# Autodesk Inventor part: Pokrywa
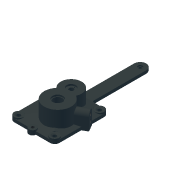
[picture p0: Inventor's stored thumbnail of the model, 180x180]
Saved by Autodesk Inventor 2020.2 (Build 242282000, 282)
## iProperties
Created: 2006-02
Part Number: Pokrywa
Document SubType Name: Modeling
Designer: F.Stasiak
Density: 1 g/cm^3
Material: Ogólny
Appearance: Brąz armatni (nowy/polerowany)
Manager: www.cadconsulting.pl
Company: Fabian Stasiak CAD Consulting
Author: F.Stasiak
Subject: Zbiór ćwiczeń. Autodesk Inventor 2020. Kurs podstawowy
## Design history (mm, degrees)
sketch "Szkic1"
  geometry: L1 (-75, 90)-(75, 90); L2 (75, 90)-(75, -90); L3 (75, -90)-(-75, -90); L4 (-75, -90)-(-75, 90); L5 (0, 90)-(0, -90); L6 (-20, 90)-(-20, 290); L7 (-20, 290)-(20, 290); L8 (20, 290)-(20, 90); L9 (0, 290)-(0, 90); 2 further points
  constraints: 18 end point, 4 midpoint, 4 perpendicular, 3 parallel, 2 point on line, 1 coincident, 1 horizontal
  dimensions: "d0" = 150 distance of L2.end L3.end; "d1" = 180 distance of L1.end L2.end; "d173" = 380 distance between parallel lines of L7 L3; "d174" = 40 distance of L6.end L7.end
extrude "Wyciągnięcie proste1" new body sketch "Szkic1" distance "d2" = 10; taper "d3" = 0 deg
node "Płaszczyzna konstrukcyjna1"
sketch "Szkic4"
  geometry: L1 (75, 90)-(75, -90) reference; L2 (-75, 90)-(75, 90) reference; L3 (-75, -90)-(-75, 90) reference; L4 (75, -90)-(-75, -90) reference; L5 (-15, 30)-(15, 30); L6 (15, 30)-(15, -30); L7 (15, -30)-(-15, -30); L8 (-15, -30)-(-15, 30)
  constraints: 8 end point, 3 other
feature "Wyciągnięcie złożone1" sketch "Szkic4" dims "d17" = 0, "d18" = 90 deg, "d19" = 0, "d20" = 90 deg
  node "Krawędzie1"
sketch "Szkic5"
  geometry: C1 r 45 at (-15, -20); 1 further point
  constraints: 1 centre point
  dimensions: "d21" = 90 diameter of C1
extrude "Wyciągnięcie proste4" join sketch "Szkic5" distance "d24" = 70; taper "d25" = 0 deg
sketch "Szkic6"
  geometry: C1 r 35 at (5, 45); 1 further point
  constraints: 1 centre point
  dimensions: "d26" = 70 diameter of C1
extrude "Wyciągnięcie proste5" join sketch "Szkic6" distance "d29" = 60; taper "d30" = 0 deg
fillet "Zaokrąglenie4" dims "d33" = 15
extrude "Wyciągnięcie proste25" join sketch "Szkic1" distance "d175" = 10; taper "d176" = 0 deg
fillet "Zaokrąglenie16" dims "d177" = 5, "d178" = 20
hole "Otwór8" diameter "d181" = 10; stored, may be unused: countersink angle "d185" = 90 deg, drill point angle "d187" = 118 deg; dims "d179" = 10, "d180" = 10, "d182" = 6, "d183" = 15, "d184" = 4, "d186" = 8
feature "Skorupa1" dims "d35" = 3
sketch "Szkic13"
  geometry: C1 r 15 at (-60, 75); C2 r 15 at (60, 75); C3 r 15 at (60, -75); C4 r 15 at (-60, -75); A1 r 15 centre (-60, 75) between (-60, 90) and (-75, 75) reference; A2 r 15 centre (60, 75) between (75, 75) and (60, 90) reference; A3 r 15 centre (-60, -75) between (-75, -75) and (-60, -90) reference; A4 r 15 centre (60, -75) between (60, -90) and (75, -75) reference
  constraints: 4 centre point, 4 coincident, 4 concentric
extrude "Wyciągnięcie proste11" join sketch "Szkic13" distance "d55" = 15; taper "d56" = 0 deg
sketch "Szkic14"
  geometry: C1 r 15 at (-60, -75); C2 r 15 at (60, -75); C3 r 15 at (60, 75); C4 r 15 at (-60, 75); A1 r 15 centre (60, -75) between (45.858, -70) and (55, -60.858) reference; A2 r 15 centre (-60, -75) between (-55, -60.858) and (-45.858, -70) reference; A3 r 15 centre (-60, 75) between (-45.858, 70) and (-55, 60.858) reference; A4 r 15 centre (60, 75) between (55, 60.858) and (45.858, 70) reference
  constraints: 4 centre point, 4 coincident, 4 concentric
extrude "Wyciągnięcie proste12" cut sketch "Szkic14" distance "d57" = 15; taper "d58" = 0 deg
fillet "Zaokrąglenie10" dims "d60" = 3
node "Oś konstrukcyjna2"
node "Płaszczyzna konstrukcyjna4"
node "Płaszczyzna konstrukcyjna5"
sketch "Szkic21"
  geometry: L1 (0, -52.272)-(0, 77.631) reference; L2 (15, -14)-(15, 14); L3 (15, 14)-(40, 14); L4 (40, -14)-(15, -14); L5 (-7, 0)-(91, 0) reference; A1 r 14 centre (40, 0) between (40, -14) and (40, 14)
  constraints: 6 end point, 2 perpendicular, 2 point on circle, 2 tangent, 1 centre point, 1 parallel, 1 point on line
  dimensions: "d92" = 14 radius of A1; "d93" = 25 distance of L4.start L2.start; "d96" = 40 distance from line of L1 A1.centre
extrude "Wyciągnięcie proste18" join sketch "Szkic21" stored distance "d94" = 10; taper "d95" = 0 deg; dims "d21" = 90
sketch "Szkic22"
  geometry: L1 (0, 18.644)-(0, 0) reference; L2 (-22.282, 31.509)-(0, 18.644) reference; L3 (-22.282, 31.509)-(-36.282, 7.26) reference; L4 (-36.282, 7.26)-(-4.037, -11.356) reference; A1 r 45 centre (40, -20.616) between (0, 0) and (-4.037, -11.356) reference
extrude "Wyciągnięcie proste19" join sketch "Szkic22" stored distance "d97" = 10; taper "d98" = 0 deg
sketch "Szkic23"
  geometry: L1 (-75, 30.807)-(-75, -1.525) reference; L2 (-75, 30.807)-(-77.282, 32.124) reference; L3 (-77.282, 32.124)-(-91.282, 7.876) reference; L4 (-91.282, 7.876)-(-75, -1.525) reference
extrude "Wyciągnięcie proste20" join sketch "Szkic23" stored distance "d99" = 10; taper "d100" = 0 deg
hole "Otwór1" diameter "d103" = 10.106; stored, may be unused: countersink angle "d107" = 90 deg, drill point angle "d109" = 118 deg; dims "d101" = 10, "d102" = 10, "d104" = 6, "d105" = 4, "d106" = 2, "d108" = 20
sketch "Szkic24"
  geometry: L1 (-40, 0)-(-20, 0); C1 r 5.053 at (-40, 0) reference; 1 further point
  constraints: 2 end point, 1 coincident, 1 horizontal
  dimensions: "d110" = 20 distance of L1.start L1.end
hole "Otwór2" sketch "Szkic24" at (-20, 0) diameter "d111" = 10.106; stored, may be unused: countersink angle "d115" = 90 deg, drill point angle "d117" = 118 deg; dims "d112" = 6, "d113" = 4, "d114" = 2, "d116" = 20
sketch "Szkic25"
  geometry: C1 r 42 at (0, 0) reference; C2 r 20 at (0, 0)
  constraints: 1 centre point, 1 coincident
  dimensions: "d118" = 40 diameter of C2
extrude "Wyciągnięcie proste21" join sketch "Szkic25" distance "d119" = 30; taper "d120" = 0 deg
hole "Otwór3" diameter "d123" = 30; stored, may be unused: countersink angle "d127" = 90 deg, drill point angle "d129" = 118 deg; dims "d121" = 10, "d122" = 10, "d124" = 6, "d125" = 35, "d126" = 5, "d128" = 8
sketch "Szkic26"
  geometry: C1 r 17.5 at (0, 0); A1 r 42 centre (0, -68.007) between (14.427, -28.563) and (-14.427, -28.563) reference; A2 r 32 centre (0, 0) between (14.427, -28.563) and (-14.427, -28.563) reference
  constraints: 1 centre point, 1 coincident
  dimensions: "d130" = 35 diameter of C1
extrude "Wyciągnięcie proste22" join sketch "Szkic26" distance "d131" = 30; taper "d132" = 0 deg
hole "Otwór4" diameter "d135" = 15; stored, may be unused: countersink angle "d139" = 90 deg, drill point angle "d141" = 118 deg; dims "d133" = 10, "d134" = 10, "d136" = 6, "d137" = 30, "d138" = 5, "d140" = 8
sketch "Szkic27"
  geometry: A1 r 15 centre (-60, -75) between (-55, -60.858) and (-45.858, -70) reference; A2 r 15 centre (-60, -75) between (-45.858, -70) and (-55, -60.858) reference; A3 r 15 centre (60, -75) between (45.858, -70) and (55, -60.858) reference; A4 r 15 centre (60, -75) between (55, -60.858) and (45.858, -70) reference; A5 r 15 centre (60, 75) between (55, 60.858) and (45.858, 70) reference; A6 r 15 centre (60, 75) between (45.858, 70) and (55, 60.858) reference; A7 r 15 centre (-60, 75) between (-60, 90) and (-75, 75) reference
hole "Otwór5" sketch "Szkic27" at (-60, -75), (60, -75), (60, 75), (-60, 75) diameter "d142" = 12; stored, may be unused: countersink angle "d146" = 120 deg, drill point angle "d148" = 118 deg; dims "d143" = 6, "d144" = 20, "d145" = 5, "d147" = 8
sketch "Szkic29"
  geometry: L1 (-60, -90)-(60, -90) reference; L2 (44.412, -87)-(-44.412, -87) reference; L3 (0, -87)-(0, -90); C1 r 12.5 at (0, -88.5)
  constraints: 3 midpoint, 2 end point, 1 centre point
  dimensions: "d152" = 25 diameter of C1
extrude "Wyciągnięcie proste24" join sketch "Szkic29" distance "d153" = 15; taper "d154" = 0 deg
fillet "Zaokrąglenie15" dims "d155" = 4
hole "Otwór6" diameter "d158" = 9.376; stored, may be unused: countersink angle "d162" = 120 deg, drill point angle "d164" = 118 deg; dims "d156" = 10, "d157" = 10, "d159" = 6, "d160" = 20, "d161" = 5, "d163" = 8
sketch "Szkic30"
  geometry: L1 (0, 0)-(0, 11); C1 r 7.5 at (0, 0) reference; 1 further point
  constraints: 2 end point, 1 coincident, 1 vertical
  dimensions: "d165" = 11 distance of L1.start L1.end
hole "Otwór7" sketch "Szkic30" at (0, 11) diameter "d166" = 3; stored, may be unused: countersink angle "d170" = 120 deg, drill point angle "d172" = 118 deg; dims "d167" = 6, "d168" = 4, "d169" = 5, "d171" = 8
node "Bryła1"
node "Korpusy bryłowe"
node "Korpusy powierzchniowe"
node "Pętla rzutowana1"
node "Pętla rzutowana5"
node "Pętla rzutowana6"
node "Pętla rzutowana7"
node "Pętla rzutowana8"
node "Pętla rzutowana9"
node "Pętla rzutowana10"
node "Pętla rzutowana11"
other parameters: "d15" = 15, "d90" = 30 deg
